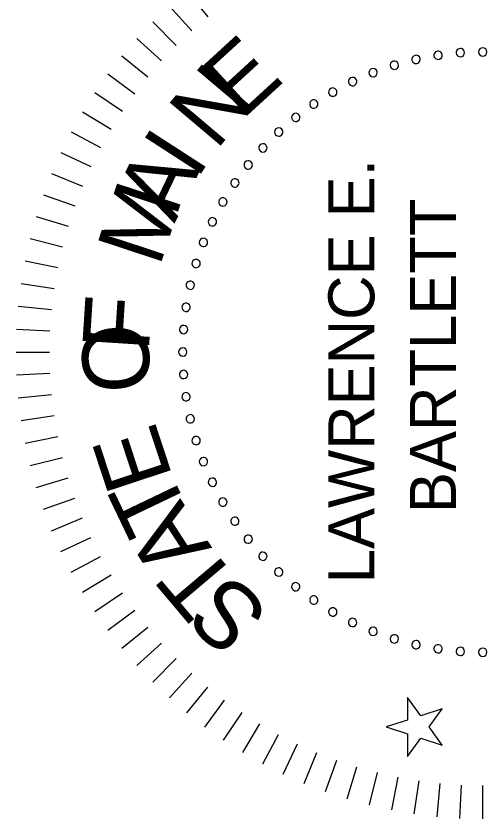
# Model space of a CAD drawing. Extents: x 916060 to 916918, y 329833 to 330383.
# Drawn here: x 916852.92 to 916873.01, y 330206.89 to 330241.13 of the extents above; entities that cross this region are included whole.
import ezdxf

# ---------------------------------------------------------------- set-up
doc = ezdxf.new("R2010")
doc.units = 0
doc.layers.add('Border', color=7, linetype='Continuous')
doc.layers.add('Default', color=7, linetype='Continuous')

# ---------------------------------------------------------------- blocks, each defined once
blk = doc.blocks.new('STAMP')
at = {"layer": 'Default'}
for p, q in [((-0.00039082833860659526, 0.009455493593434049), (-0.00036291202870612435, 0.008887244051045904)), ((-4.996003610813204e-18, 0.009465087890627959), (-4.996003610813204e-18, 0.008896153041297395)), ((0.0003908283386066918, 0.009455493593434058), (0.0003629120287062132, 0.008887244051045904)), ((-0.0011687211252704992, 0.009378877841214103), (-0.0010852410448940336, 0.008816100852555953)), ((-0.0007807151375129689, 0.009426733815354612), (-0.0007249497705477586, 0.00886053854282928)), ((0.0007807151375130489, 0.009426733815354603), (0.0007249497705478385, 0.00886053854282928)), ((0.0011687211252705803, 0.009378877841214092), (0.0010852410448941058, 0.008816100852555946)), ((-0.0019353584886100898, 0.009226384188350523), (-0.0017971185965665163, 0.008674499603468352)), ((-0.0015539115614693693, 0.009312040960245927), (-0.0014429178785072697, 0.00875403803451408)), ((0.001553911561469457, 0.009312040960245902), (0.001442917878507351, 0.008754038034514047)), ((0.0019353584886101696, 0.009226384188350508), (0.0017971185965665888, 0.008674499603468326)), ((-0.002312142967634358, 0.009122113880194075), (-0.002146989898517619, 0.008577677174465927)), ((0.0023121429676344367, 0.00912211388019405), (0.0021469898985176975, 0.008577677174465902)), ((-0.0026833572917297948, 0.008999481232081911), (-0.0024916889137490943, 0.00846380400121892)), ((0.002683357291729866, 0.008999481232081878), (0.0024916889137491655, 0.008463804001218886)), ((-0.003048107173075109, 0.008858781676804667), (-0.0028303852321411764, 0.008333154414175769)), ((0.00304810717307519, 0.008858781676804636), (0.002830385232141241, 0.008333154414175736)), ((-0.003405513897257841, 0.008700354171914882), (-0.0031622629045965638, 0.008186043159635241)), ((0.0034055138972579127, 0.008700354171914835), (0.0031622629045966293, 0.008186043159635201)), ((-0.0037547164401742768, 0.008524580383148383), (-0.0034865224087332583, 0.00802282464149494)), ((0.003754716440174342, 0.008524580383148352), (0.0034865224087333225, 0.008022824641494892)), ((-0.004094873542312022, 0.008331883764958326), (-0.003802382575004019, 0.0078438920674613)), ((0.0040948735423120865, 0.008331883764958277), (0.0038023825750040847, 0.007843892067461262)), ((-0.004425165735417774, 0.008122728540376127), (-0.004109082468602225, 0.0076496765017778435)), ((0.004425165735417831, 0.008122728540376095), (0.004109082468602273, 0.007649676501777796)), ((-0.004744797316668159, 0.007897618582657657), (-0.004405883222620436, 0.007440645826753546)), ((0.004744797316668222, 0.007897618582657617), (0.004405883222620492, 0.007440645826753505)), ((-0.0050529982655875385, 0.0076570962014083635), (-0.004692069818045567, 0.007217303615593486)), ((0.005052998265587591, 0.0076570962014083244), (0.004692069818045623, 0.0072173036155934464)), ((-0.005349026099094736, 0.007401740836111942), (-0.004966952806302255, 0.006980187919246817)), ((0.0053490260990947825, 0.0074017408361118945), (0.004966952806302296, 0.00698018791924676)), ((-0.0056321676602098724, 0.00713216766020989), (-0.00522986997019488, 0.006729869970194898)), ((0.005632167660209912, 0.007132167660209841), (0.005229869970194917, 0.006729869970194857)), ((-0.005901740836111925, 0.006849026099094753), (-0.005480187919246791, 0.006466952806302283)), ((0.005901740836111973, 0.0068490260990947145), (0.00548018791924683, 0.006466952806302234)), ((-0.006157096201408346, 0.006552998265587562), (-0.005717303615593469, 0.006192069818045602)), ((0.006157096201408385, 0.006552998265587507), (0.005717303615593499, 0.006192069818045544)), ((-0.00639761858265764, 0.006244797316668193), (-0.0059406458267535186, 0.0059058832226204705)), ((-0.006622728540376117, 0.0059251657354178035), (-0.006149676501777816, 0.005609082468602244)), ((-0.006831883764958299, 0.005594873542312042), (-0.0063438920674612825, 0.0053023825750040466)), ((-0.007024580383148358, 0.005254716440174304), (-0.006522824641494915, 0.004986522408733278)), ((-0.007200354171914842, 0.00490551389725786), (-0.006686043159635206, 0.004662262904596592)), ((-0.0073587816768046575, 0.004548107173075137), (-0.006833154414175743, 0.004330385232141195)), ((-0.007499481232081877, 0.004183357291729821), (-0.006963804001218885, 0.003991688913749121)), ((-0.007622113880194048, 0.0038121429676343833), (-0.007077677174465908, 0.003646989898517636)), ((-0.007726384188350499, 0.0034353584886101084), (-0.007174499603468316, 0.003297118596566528)), ((-0.0078120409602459, 0.0030539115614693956), (-0.007254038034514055, 0.0029429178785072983)), ((-0.006396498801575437, 0.0031478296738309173), (-0.006515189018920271, 0.0027825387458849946)), ((-0.006277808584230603, 0.0027825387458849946), (-0.006396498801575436, 0.0031478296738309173)), ((-0.006515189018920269, 0.0027825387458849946), (-0.006899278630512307, 0.0027825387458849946)), ((-0.006899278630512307, 0.0027825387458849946), (-0.006588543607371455, 0.002556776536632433)), ((-0.005893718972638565, 0.0027825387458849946), (-0.006277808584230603, 0.0027825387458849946)), ((-0.006204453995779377, 0.002556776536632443), (-0.005893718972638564, 0.0027825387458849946)), ((-0.007878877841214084, 0.002668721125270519), (-0.007316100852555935, 0.0025852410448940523)), ((-0.006588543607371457, 0.002556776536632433), (-0.00670723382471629, 0.0021914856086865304)), ((-0.006085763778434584, 0.0021914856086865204), (-0.006204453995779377, 0.002556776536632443)), ((-0.006707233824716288, 0.0021914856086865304), (-0.006396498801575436, 0.0024172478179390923)), ((-0.006396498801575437, 0.0024172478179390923), (-0.006085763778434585, 0.0021914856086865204)), ((-0.007926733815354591, 0.00228071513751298), (-0.007360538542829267, 0.0022249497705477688)), ((-0.007955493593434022, 0.0018908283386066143), (-0.007387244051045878, 0.0018629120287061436)), ((-0.007965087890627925, 0.0015000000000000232), (-0.0073961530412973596, 0.0015000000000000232))]:
    blk.add_line(p, q, dxfattribs=at)
blk.add_lwpolyline([(-0.006277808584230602, 0.0027825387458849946), (-0.006396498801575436, 0.0031478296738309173), (-0.006515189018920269, 0.0027825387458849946), (-0.006899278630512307, 0.0027825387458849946), (-0.006588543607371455, 0.002556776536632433), (-0.006707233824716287, 0.0021914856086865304), (-0.006396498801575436, 0.0024172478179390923), (-0.0060857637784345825, 0.0021914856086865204), (-0.006204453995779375, 0.002556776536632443), (-0.005893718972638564, 0.0027825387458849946)], close=True, dxfattribs=at)
for centre, radius, start, end in [((-0.0007631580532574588, 0.006563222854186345), 7.111685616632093e-05, 8.571428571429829, 188.57142857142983), ((-0.0003826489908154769, 0.006606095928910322), 7.111685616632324e-05, 4.285714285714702, 184.2857142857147), ((-0.0003826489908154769, 0.006606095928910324), 7.111685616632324e-05, 184.28571428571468, 4.2857142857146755), ((-4.718447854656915e-18, 0.006620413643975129), 7.111685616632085e-05, 0, 180), ((-4.718447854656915e-18, 0.006620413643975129), 7.111685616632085e-05, 180, 0), ((0.0003826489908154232, 0.0066060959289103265), 7.111685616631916e-05, 175.71428571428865, 355.7142857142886), ((0.0003826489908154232, 0.0066060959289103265), 7.111685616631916e-05, 355.7142857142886, 175.71428571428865), ((0.0007631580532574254, 0.006563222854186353), 7.111685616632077e-05, 351.42857142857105, 171.42857142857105), ((-0.0015092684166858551, 0.006392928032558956), 7.111685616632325e-05, 17.142857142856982, 197.142857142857), ((-0.001139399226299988, 0.006492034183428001), 7.111685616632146e-05, 12.857142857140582, 192.8571428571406), ((-0.001139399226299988, 0.006492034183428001), 7.111685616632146e-05, 192.85714285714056, 12.857142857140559), ((-0.0007631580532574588, 0.006563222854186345), 7.111685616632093e-05, 188.57142857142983, 8.571428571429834), ((0.0007631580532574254, 0.006563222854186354), 7.111685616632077e-05, 171.42857142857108, 351.4285714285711), ((0.0011393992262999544, 0.006492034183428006), 7.111685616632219e-05, 167.1428571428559, 347.14285714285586), ((0.0011393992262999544, 0.006492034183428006), 7.111685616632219e-05, 347.14285714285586, 167.1428571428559), ((0.0015092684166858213, 0.006392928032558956), 7.111685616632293e-05, 342.85714285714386, 162.85714285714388), ((-0.0018706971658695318, 0.006266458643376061), 7.111685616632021e-05, 21.42857142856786, 201.42857142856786), ((-0.0015092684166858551, 0.006392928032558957), 7.111685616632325e-05, 197.14285714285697, 17.14285714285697), ((0.0015092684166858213, 0.006392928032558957), 7.111685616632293e-05, 162.85714285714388, 342.8571428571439), ((0.0018706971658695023, 0.006266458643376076), 7.111685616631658e-05, 338.571428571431, 158.571428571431), ((-0.0022216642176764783, 0.0061133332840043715), 7.111685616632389e-05, 25.714285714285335, 205.71428571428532), ((-0.0018706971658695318, 0.006266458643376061), 7.111685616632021e-05, 201.42857142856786, 21.428571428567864), ((0.0018706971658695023, 0.006266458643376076), 7.111685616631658e-05, 158.571428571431, 338.571428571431), ((0.002221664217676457, 0.006113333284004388), 7.11168561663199e-05, 334.2857142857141, 154.2857142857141), ((-0.0022216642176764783, 0.006113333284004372), 7.111685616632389e-05, 205.71428571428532, 25.714285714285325), ((0.002221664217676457, 0.006113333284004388), 7.11168561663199e-05, 154.2857142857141, 334.2857142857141), ((-0.0025602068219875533, 0.005934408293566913), 7.111685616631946e-05, 30.000000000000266, 210.00000000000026), ((-0.0025602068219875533, 0.005934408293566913), 7.111685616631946e-05, 210.00000000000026, 30.000000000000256), ((0.002560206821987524, 0.005934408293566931), 7.11168561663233e-05, 150.00000000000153, 330.00000000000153), ((0.002560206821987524, 0.005934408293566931), 7.111685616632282e-05, 330.0000000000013, 150.0000000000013), ((-0.002884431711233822, 0.005730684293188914), 7.11168561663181e-05, 34.28571428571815, 214.28571428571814), ((-0.002884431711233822, 0.005730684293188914), 7.111685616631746e-05, 214.2857142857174, 34.285714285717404), ((0.0028844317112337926, 0.005730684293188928), 7.111685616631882e-05, 145.71428571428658, 325.7142857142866), ((0.0028844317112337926, 0.005730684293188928), 7.111685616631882e-05, 325.7142857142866, 145.71428571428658), ((-0.003192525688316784, 0.0055033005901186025), 7.11168561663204e-05, 38.57142857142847, 218.57142857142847), ((-0.003192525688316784, 0.0055033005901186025), 7.111685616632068e-05, 218.57142857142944, 38.571428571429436), ((0.0031925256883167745, 0.00550330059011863), 7.111685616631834e-05, 141.42857142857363, 321.4285714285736), ((0.0031925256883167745, 0.00550330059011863), 7.111685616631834e-05, 321.4285714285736, 141.42857142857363), ((-0.0034827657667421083, 0.005253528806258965), 7.111685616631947e-05, 42.857142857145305, 222.8571428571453), ((-0.0034827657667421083, 0.005253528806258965), 7.111685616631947e-05, 222.8571428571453, 42.857142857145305), ((0.003482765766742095, 0.005253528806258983), 7.111685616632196e-05, 137.1428571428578, 317.1428571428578), ((0.003482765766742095, 0.005253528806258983), 7.111685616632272e-05, 317.1428571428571, 137.14285714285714), ((-0.0037535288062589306, 0.004982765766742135), 7.11168561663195e-05, 47.142857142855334, 227.14285714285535), ((-0.0037535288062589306, 0.004982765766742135), 7.11168561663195e-05, 227.14285714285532, 47.14285714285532), ((0.0037535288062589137, 0.004982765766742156), 7.111685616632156e-05, 132.85714285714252, 312.85714285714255), ((0.0037535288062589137, 0.004982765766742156), 7.111685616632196e-05, 312.8571428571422, 132.8571428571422), ((-0.004003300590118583, 0.004692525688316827), 7.111685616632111e-05, 51.428571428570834, 231.42857142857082), ((-0.004003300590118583, 0.004692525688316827), 7.111685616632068e-05, 231.42857142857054, 51.428571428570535), ((0.004003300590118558, 0.004692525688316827), 7.111685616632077e-05, 128.57142857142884, 308.57142857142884), ((0.004003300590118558, 0.004692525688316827), 7.111685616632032e-05, 308.5714285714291, 128.5714285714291), ((-0.0042306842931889, 0.004384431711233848), 7.11168561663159e-05, 55.71428571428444, 235.71428571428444), ((-0.0042306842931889, 0.004384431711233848), 7.111685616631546e-05, 235.7142857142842, 55.71428571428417), ((0.004230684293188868, 0.0043844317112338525), 7.111685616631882e-05, 124.28571428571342, 304.2857142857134), ((0.004230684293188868, 0.0043844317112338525), 7.111685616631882e-05, 304.2857142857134, 124.28571428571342), ((-0.004434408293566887, 0.004060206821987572), 7.111685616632e-05, 59.99999999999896, 239.99999999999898), ((-0.004434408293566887, 0.004060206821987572), 7.111685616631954e-05, 239.99999999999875, 59.999999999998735), ((0.004434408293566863, 0.004060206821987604), 7.111685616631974e-05, 120.00000000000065, 300.0000000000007), ((0.004434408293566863, 0.004060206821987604), 7.111685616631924e-05, 300.00000000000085, 120.00000000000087), ((-0.004613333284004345, 0.003721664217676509), 7.111685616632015e-05, 64.28571428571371, 244.2857142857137), ((-0.004613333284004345, 0.003721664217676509), 7.111685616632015e-05, 244.2857142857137, 64.2857142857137), ((0.004613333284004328, 0.0037216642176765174), 7.11168561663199e-05, 115.7142857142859, 295.7142857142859), ((0.004613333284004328, 0.0037216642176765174), 7.11168561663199e-05, 295.7142857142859, 115.71428571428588), ((-0.004766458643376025, 0.0033706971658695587), 7.111685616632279e-05, 68.57142857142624, 248.57142857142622), ((-0.004766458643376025, 0.0033706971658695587), 7.111685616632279e-05, 248.57142857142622, 68.57142857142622), ((0.004766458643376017, 0.0033706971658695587), 7.111685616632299e-05, 111.42857142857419, 291.4285714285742), ((0.004766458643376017, 0.0033706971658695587), 7.111685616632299e-05, 291.4285714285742, 111.42857142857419), ((-0.004892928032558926, 0.003009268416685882), 7.11168561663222e-05, 72.8571428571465, 252.8571428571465), ((-0.004892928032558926, 0.003009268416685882), 7.11168561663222e-05, 252.8571428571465, 72.8571428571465), ((0.004892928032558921, 0.003009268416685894), 7.111685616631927e-05, 107.14285714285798, 287.14285714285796), ((0.004892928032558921, 0.003009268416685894), 7.111685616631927e-05, 287.14285714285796, 107.14285714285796), ((-0.00499203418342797, 0.0026393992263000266), 7.111685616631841e-05, 77.14285714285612, 257.1428571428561), ((-0.004992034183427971, 0.0026393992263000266), 7.111685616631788e-05, 257.142857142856, 77.142857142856), ((0.004992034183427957, 0.002639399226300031), 7.111685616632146e-05, 102.85714285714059, 282.8571428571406), ((0.004992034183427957, 0.002639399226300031), 7.111685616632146e-05, 282.85714285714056, 102.85714285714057), ((-0.005063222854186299, 0.0022631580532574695), 7.111685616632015e-05, 81.42857142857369, 261.4285714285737), ((-0.005063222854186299, 0.0022631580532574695), 7.111685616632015e-05, 261.4285714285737, 81.42857142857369), ((0.005063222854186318, 0.0022631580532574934), 7.111685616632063e-05, 98.57142857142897, 278.57142857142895), ((0.005063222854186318, 0.0022631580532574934), 7.111685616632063e-05, 278.57142857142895, 98.57142857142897), ((-0.005106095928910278, 0.0018826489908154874), 7.111685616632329e-05, 85.7142857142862, 265.71428571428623), ((-0.005106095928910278, 0.0018826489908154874), 7.1116856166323e-05, 265.7142857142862, 85.71428571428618), ((0.005106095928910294, 0.0018826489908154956), 7.111685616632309e-05, 94.2857142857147, 274.2857142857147), ((0.005106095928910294, 0.0018826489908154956), 7.111685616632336e-05, 274.2857142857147, 94.28571428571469), ((-0.0051204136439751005, 0.0015000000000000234), 7.111685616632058e-05, 90, 270), ((-0.0051204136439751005, 0.0015000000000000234), 7.111685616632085e-05, 270, 90), ((0.005120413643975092, 0.0015000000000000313), 7.111685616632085e-05, 90, 270), ((0.005120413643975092, 0.0015000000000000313), 7.111685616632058e-05, 270, 90)]:
    blk.add_arc(centre, radius, start, end, dxfattribs=at)
for s, height, rotation, p in [('O', 0.0011378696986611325, 3.6537999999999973, (-0.0006627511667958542, 0.007158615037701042)), ('F', 0.0011378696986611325, 356.3462, (-7.4134925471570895e-06, 0.007201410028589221)), ('E', 0.0011378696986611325, 18.2692, (-0.0021355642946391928, 0.00678635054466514)), ('M', 0.001137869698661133, 341.7308, (0.0014314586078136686, 0.0070187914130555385)), ('T', 0.0011378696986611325, 25.576899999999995, (-0.0027590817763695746, 0.006486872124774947)), ('A', 0.0011378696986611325, 334.4231, (0.002184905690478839, 0.00676168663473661)), ('A', 0.0011378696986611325, 32.884600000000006, (-0.003341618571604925, 0.006114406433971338)), ('I', 0.0011378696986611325, 327.1154, (0.0029245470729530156, 0.00638406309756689)), ('T', 0.001137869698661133, 40.19230000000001, (-0.003928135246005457, 0.005629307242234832)), ('N', 0.001137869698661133, 319.8077, (0.003425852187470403, 0.0060536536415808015)), ('S', 0.001137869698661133, 47.49999999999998, (-0.004421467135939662, 0.00509611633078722)), ('E', 0.001137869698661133, 312.5, (0.0039441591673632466, 0.005617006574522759))]:
    blk.add_text(s, height=height, rotation=rotation, dxfattribs=at).set_placement(p)
for s, p in [('LAWRENCE E.', (-0.003944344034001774, 0.0033503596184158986)), ('BARTLETT', (-0.0027479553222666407, 0.001958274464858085))]:
    blk.add_text(s, height=0.0007851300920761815, dxfattribs=at).set_placement(p)

msp = doc.modelspace()

# ---------------------------------------------------------------- block references
at = {"layer": 'Border', "xscale": 2499.999999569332, "yscale": 2499.999999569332, "rotation": 90}
msp.add_blockref('STAMP', (916876.5782560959, 330226.80272714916), dxfattribs=at)

doc.saveas('drawing.dxf')
